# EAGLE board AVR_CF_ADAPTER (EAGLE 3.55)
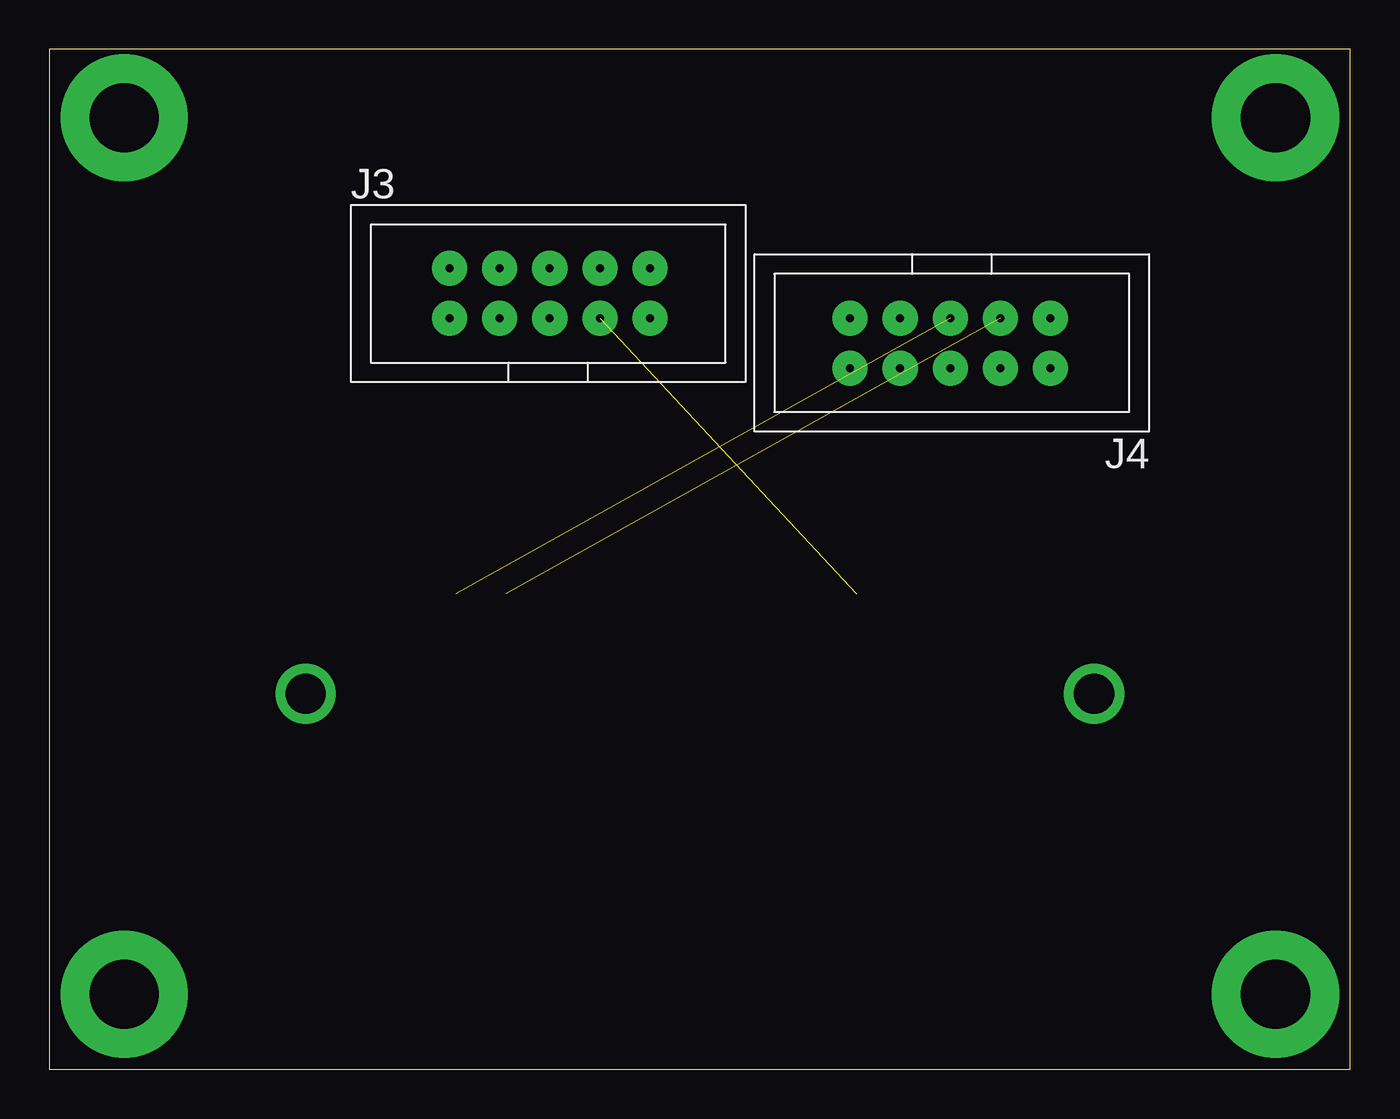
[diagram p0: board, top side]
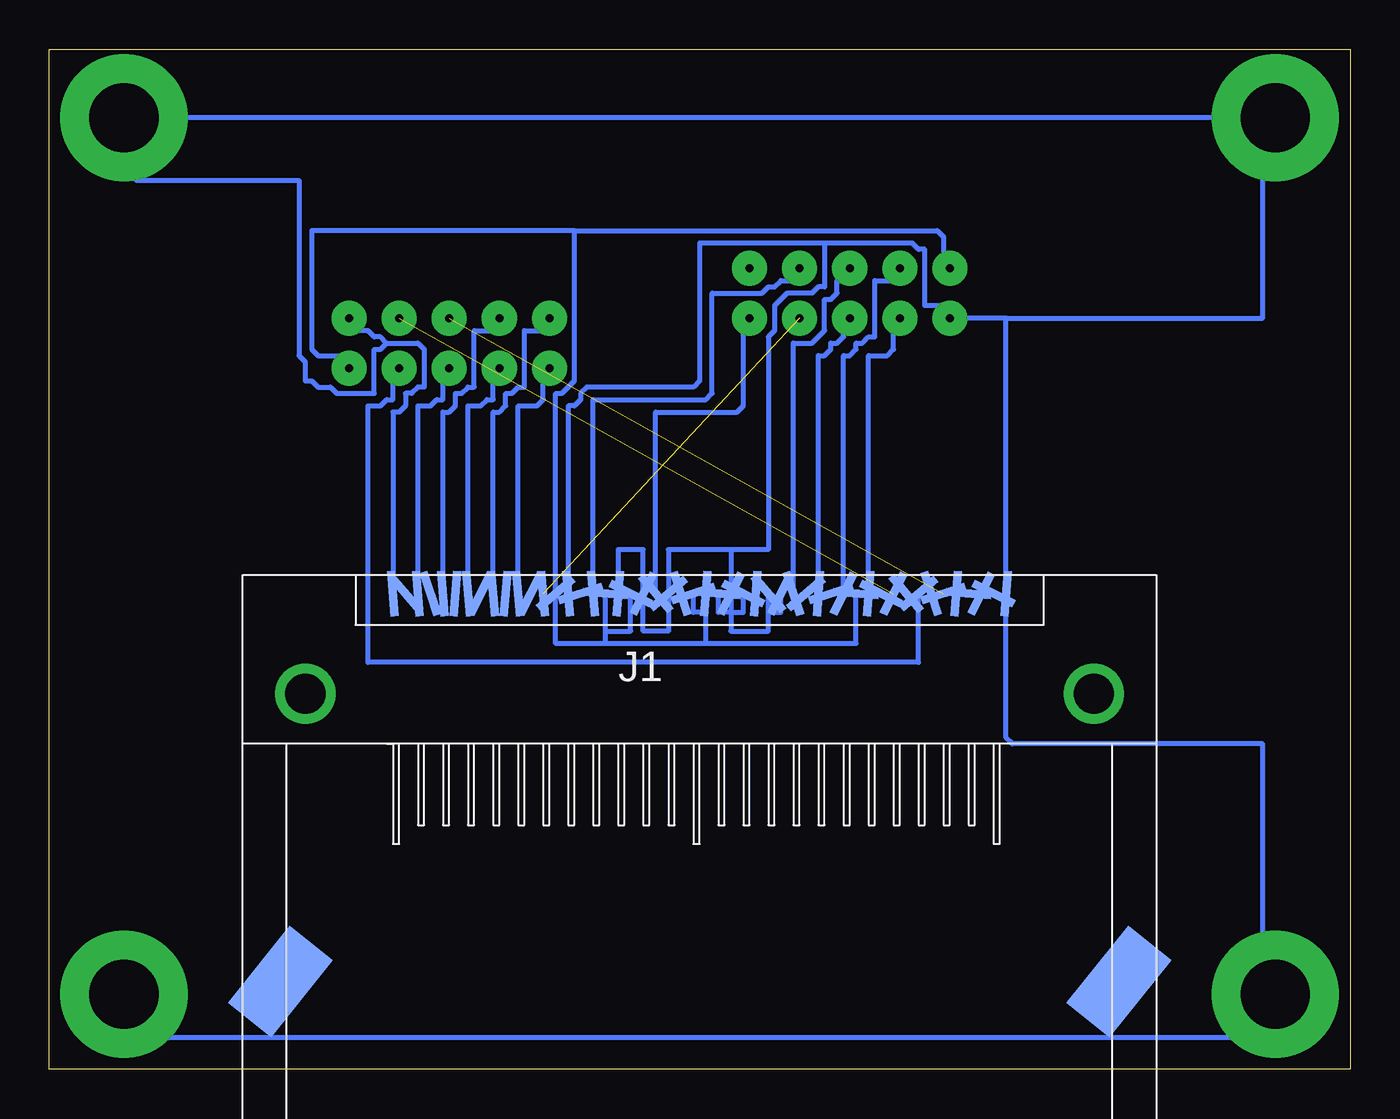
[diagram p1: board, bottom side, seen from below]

Size 66.02 x 51.74 mm. Coordinates in mm from the lower left corner, seen from the top.
Outline: 0,0 66.02,0 66.02,51.74 0,51.74 0,0
Copper layers used: Bottom

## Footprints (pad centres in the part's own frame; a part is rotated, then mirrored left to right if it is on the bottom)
SMT = drill 2.032 pad 3.048 round: @1 -20.003,-5.08; @2 20.003,-5.08 | smd 2.794 x 5.004 rotated 321.2: @3 -21.273,-19.685; @4 21.273,-19.685 | smd 0.406 x 2.311 rotated 4.3:  -15.557,0;  -4.128,0 | smd 0.406 x 2.311 rotated 4.4:  -14.287,0;  8.572,0 | smd 0.406 x 2.311 rotated 4.5:  -13.018,0;  -9.842,0 | smd 0.406 x 2.311 rotated 4.6:  -11.748,0;  2.857,0 | smd 0.406 x 2.311 rotated 4.7:  -10.477,0;  -9.207,0;  15.557,0 | smd 0.406 x 2.311 rotated 4.8:  -7.938,0 | smd 0.406 x 2.311 rotated 4.9:  -6.668,0 | smd 0.406 x 2.311 rotated 5:  -5.397,0 | smd 0.406 x 2.311 rotated 26.8:  -2.857,0 | smd 0.406 x 2.311 rotated 49.3:  -1.587,0 | smd 0.406 x 2.311 rotated 71.8:  -0.318,0 | smd 0.406 x 2.311 rotated 94.3:  0.953,0 | smd 0.406 x 2.311 rotated 116.8:  2.223,0 | smd 0.406 x 2.311 rotated 139.3:  3.493,0 | smd 0.406 x 2.311 rotated 161.8:  4.763,0 | smd 0.406 x 2.311 rotated 184.3:  6.032,0 | smd 0.406 x 2.311 rotated 206.8:  7.303,0 | smd 0.406 x 2.311 rotated 26.9:  9.842,0 | smd 0.406 x 2.311 rotated 49.4:  11.113,0 | smd 0.406 x 2.311 rotated 71.9:  12.383,0 | smd 0.406 x 2.311 rotated 94.4:  13.652,0 | smd 0.406 x 2.311 rotated 116.9:  14.922,0 | smd 0.406 x 2.311 rotated 139.4:  -14.922,0 | smd 0.406 x 2.311 rotated 161.9:  -13.652,0 | smd 0.406 x 2.311 rotated 184.4:  -12.383,0 | smd 0.406 x 2.311 rotated 206.9:  -11.113,0 | smd 0.406 x 2.311 rotated 27:  -8.572,0 | smd 0.406 x 2.311 rotated 49.5:  -7.303,0 | smd 0.406 x 2.311 rotated 72:  -6.032,0 | smd 0.406 x 2.311 rotated 94.5:  -4.763,0 | smd 0.406 x 2.311 rotated 117:  -3.493,0 | smd 0.406 x 2.311 rotated 139.5:  -2.223,0 | smd 0.406 x 2.311 rotated 162:  -0.953,0 | smd 0.406 x 2.311 rotated 184.5:  0.318,0 | smd 0.406 x 2.311 rotated 207:  1.587,0 | smd 0.406 x 2.311 rotated 27.1:  4.128,0 | smd 0.406 x 2.311 rotated 49.6:  5.397,0 | smd 0.406 x 2.311 rotated 72.1:  6.668,0 | smd 0.406 x 2.311 rotated 94.6:  7.938,0 | smd 0.406 x 2.311 rotated 117.1:  9.207,0 | smd 0.406 x 2.311 rotated 139.6:  10.477,0 | smd 0.406 x 2.311 rotated 162.1:  11.748,0 | smd 0.406 x 2.311 rotated 184.6:  13.018,0 | smd 0.406 x 2.311 rotated 207.1:  14.287,0
5 = drill 0.406 pad 1.778 round:  0,0;  2.54,0;  5.08,0;  7.62,0;  10.16,0;  10.16,2.54;  7.62,2.54;  5.08,2.54;  2.54,2.54;  0,2.54
HRUNG = drill 3.505 pad 6.452 round:  0,0

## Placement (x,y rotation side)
J1  CFLASH1  [SMT]  33.02,24.13 0 bottom
J3  8BITPORT  [5]  20.32,38.1 0 top
J4  8BITPORT  [5]  50.8,38.1 180 top
U$2  BOHRUNG  [HRUNG]  3.81,3.81 0 top
U$3  BOHRUNG  [HRUNG]  3.81,48.26 0 top
U$4  BOHRUNG  [HRUNG]  62.23,3.81 0 top
U$6  BOHRUNG  [HRUNG]  62.23,48.26 0 top

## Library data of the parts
J1 = ic_holg
J3 J4 = holg_plt
U$2-U$4 U$6 = holgnorm

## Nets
+5V: J1. J3. J4.
/CS_CF: J1. J3.
/RD: J1. J3.
/WR: J1. J3.
A0: J1. J3.
A1: J1. J3.
A2: J1. J3.
A3: J1. J3.
D0: J1. J4.
D1: J1. J4.
D2: J1. J4.
D3: J1. J4.
D4: J1. J4.
D5: J1. J4.
D6: J1. J4.
D7: J1. J4.
GND: J1. J3. J4. U$2. U$3. U$4. U$6.

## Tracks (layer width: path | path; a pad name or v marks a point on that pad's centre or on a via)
+5V
  Bottom 0.254: 37.78,22.23 36.51,22.23 36.51,24.13 | 37.78,22.23 37.78,24.13 | 37.78,21.59 40.32,21.59 40.32,24.13 40.32,34.29 40.01,34.29 39.37,34.92 39.37,42.55 | 37.78,21.59 37.78,22.23 | 32.7,21.59 25.08,21.59 25.08,24.13 | 32.7,21.59 32.7,23.18 | 32.7,23.18 33.34,23.18 33.34,24.13 | 32.7,23.18 32.7,24.13 | 32.7,21.59 37.78,21.59 | 39.37,42.55 20.95,42.55 20.64,42.23 20.64,41.27 J3. | 39.37,42.55 52.7,42.55 52.7,36.51 52.39,36.2 51.12,36.2 J4.
/CS_CF  (1 unrouted)
/RD
  Bottom 0.254: 38.42,24.13 38.42,33.97 32.7,33.97 32.38,34.29 32.38,39.37 29.84,39.37 29.53,39.69 29.21,39.69 28.89,40.01 28.26,40.01 27.94,40.64
/WR
  Bottom 0.254: 35.24,24.13 35.24,33.34 31.11,33.34 30.8,33.66 30.8,37.47 30.48,38.1
A0
  Bottom 0.254: 24.45,24.13 24.45,36.2 23.5,36.2 23.18,36.51 23.18,37.47 22.86,38.1
A1
  Bottom 0.254: 25.72,24.13 25.72,36.2 25.4,36.2 25.08,36.51 25.08,36.83 24.77,36.83 24.45,37.15 24.13,37.15 24.13,40.01 23.18,40.01 22.86,40.64
A2
  Bottom 0.254: 26.99,24.13 26.99,36.2 26.67,36.2 26.35,36.51 26.35,36.83 26.04,36.83 25.72,37.15 25.72,37.47 25.4,38.1
A3
  Bottom 0.254: 28.26,24.13 28.26,36.83 27.3,36.83 26.67,37.47 26.67,39.05 26.35,39.05 26.04,39.37 26.04,40.01 25.72,40.01 25.4,40.64
D0  (1 unrouted)
D1
  Bottom 0.254: 21.91,24.13 21.91,20.64 49.85,20.64 49.85,33.66 49.21,33.66 48.9,33.97 48.58,33.97 48.58,34.92 48.26,35.56
D2  (1 unrouted)
D3
  Bottom 0.254: 47.31,24.13 47.31,33.66 46.67,33.66 46.35,33.97 46.04,33.97 46.04,34.92 45.72,35.56
D4
  Bottom 0.254: 46.04,24.13 46.04,33.34 45.72,33.34 45.4,33.66 45.4,34.29 45.09,34.29 44.77,34.61 44.45,34.61 44.45,37.47 43.5,37.47 43.18,38.1
D5
  Bottom 0.254: 44.77,24.13 44.77,33.66 44.13,33.66 43.81,33.97 43.5,33.97 43.5,34.92 43.18,35.56
D6
  Bottom 0.254: 43.5,24.13 43.5,33.34 43.18,33.34 42.86,33.66 42.86,34.29 42.55,34.29 42.23,34.61 41.91,34.61 41.91,37.47 40.96,37.47 40.64,38.1
D7
  Bottom 0.254: 42.23,24.13 42.23,33.66 41.27,33.66 40.96,33.97 40.96,34.92 40.64,35.56
GND
  Bottom 0.254: U$4. 60.01,1.59 6.03,1.59 U$2. 4.45,6.99 4.45,16.51 17.14,16.51 17.46,16.83 J1. 17.46,38.1 | 48.9,36.83 47.31,36.83 46.99,36.51 46.99,34.61 47.31,34.61 47.62,34.29 47.94,34.29 47.94,33.66 48.26,33.34 48.58,33.34 48.58,24.13 | 48.9,36.83 49.21,37.15 49.53,37.15 49.85,37.47 50.48,37.47 50.8,38.1 | 37.15,24.13 37.15,26.35 35.88,26.35 35.88,24.13 35.88,22.23 34.61,22.23 34.61,24.13 34.61,26.35 31.43,26.35 | 29.53,23.18 28.89,23.18 28.89,24.13 | 31.43,23.18 30.8,23.18 30.8,24.13 | 31.43,23.18 32.07,23.18 32.07,24.13 | 29.53,23.18 29.53,22.23 31.43,22.23 31.43,23.18 | 29.53,23.18 29.53,24.13 | 31.43,23.18 31.43,24.13 31.43,26.35 | 17.46,38.1 20.32,38.1 20.64,38.73 21.59,38.73 21.59,41.59 21.91,41.59 22.23,41.91 26.67,41.91 | 26.67,41.91 33.02,41.91 33.02,34.92 33.34,34.61 38.73,34.61 39.05,34.29 39.05,33.97 39.37,33.66 39.69,33.66 39.69,24.13 | 31.43,26.35 29.53,26.35 29.53,37.15 29.21,37.47 29.21,38.73 28.57,39.37 27.3,39.37 26.99,39.69 26.67,39.69 26.67,41.91 | 17.46,38.1 4.45,38.1 4.45,45.09 U$3. U$6. 61.59,45.09 53.34,45.09 53.34,36.2 53.02,35.88 53.02,34.92 52.7,34.92 52.39,34.61 51.75,34.61 51.44,34.29 49.53,34.29 49.53,36.51 49.21,36.51 48.9,36.83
